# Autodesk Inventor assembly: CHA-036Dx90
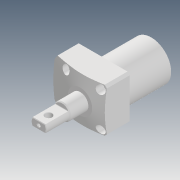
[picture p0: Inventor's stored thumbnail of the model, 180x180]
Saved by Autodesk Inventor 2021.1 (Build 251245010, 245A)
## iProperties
Created: 2019-12
Part Number: CHA-036Dx90
Description: STEP AP203
Document SubType Name: Assembly
Designer: user
Title: CHA-036Dx90.STEP
Revision Number: ÈÎºÎ
Sending System: SolidWorks 2017
Preprocessor: SwSTEP 2.0
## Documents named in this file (3)
- D:\Vault_2016\Projekty\Clamptek\Hydraulic\CHA\CHA\CHA-036\Inventor\CHA-036Dx90\CHA-036Dx90.iam
- D:\Vault_2016\Projekty\Clamptek\Hydraulic\CHA\CHA\CHA-036\Inventor\CHA-036Dx90\CHA-036±¾Ìå.ipt
- D:\Vault_2016\Projekty\Clamptek\Hydraulic\CHA\CHA\CHA-036\Inventor\CHA-036Dx90\CHA-036D(Ë«±Û£©»îÈû¸Ë_1.ipt
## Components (2 placed, 2 different names)
1. CHA-036±¾Ìå_1
2. CHA-036D(Ë«±Û£©»îÈû¸Ë_1_2
